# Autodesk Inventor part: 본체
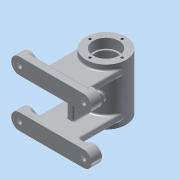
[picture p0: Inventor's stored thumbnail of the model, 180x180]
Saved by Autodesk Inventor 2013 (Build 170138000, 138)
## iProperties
Created: 2015-11
Part Number: 본체
Material: 알루미늄 6061
Document SubType Name: Modeling
Designer: user-11
Density: 2.71 g/cm^3
Mass: 359.522 g
Surface Area: 461.614 cm^2
Volume: 132.665 cm^3
Author: user-11
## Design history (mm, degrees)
sketch "스케치1"
  geometry: 1 further point
sketch "스케치2"
  geometry: 1 further point
sketch "스케치3"
  geometry: C1 r 25 at (0, 0); 1 further point
  constraints: 1 centre point, 1 coincident
  dimensions: "d0" = 50 diameter of C1
extrude "돌출1" new body sketch "스케치3" stored distance "d2" = 70; taper "d3" = 0 deg
node "작업 평면1"
sketch "스케치4"
  geometry: C1 r 21 at (0, 0); 1 further point
  constraints: 1 centre point, 1 coincident
  dimensions: "d4" = 42 diameter of C1
extrude "돌출2" cut sketch "스케치4" stored distance "d6" = 42; taper "d7" = 0 deg
sketch "스케치5"
  geometry: C1 r 25 at (0, 0) reference; C2 r 14 at (0, 0)
  constraints: 1 centre point, 1 coincident
  dimensions: "d8" = 28 diameter of C2
extrude "돌출3" cut sketch "스케치5" stored distance "d10" = 42; taper "d11" = 0 deg
sketch "스케치6"
  geometry: C1 r 14 at (0, 0) reference; C2 r 25 at (0, 0) reference; C3 r 16 at (0, 0)
  constraints: 1 centre point, 1 coincident
  dimensions: "d12" = 32 diameter of C3
extrude "돌출4" cut sketch "스케치6" distance "d14" = 12; taper "d15" = 0 deg
sketch "스케치7"
  geometry: C1 r 14 at (0, 0) reference; C2 r 25 at (0, 0) reference; C3 r 16 at (0, 0)
  constraints: 1 centre point, 1 coincident
  dimensions: "d16" = 32 diameter of C3
extrude "돌출5" cut sketch "스케치7" distance "d18" = 12; taper "d19" = 0 deg
node "작업 평면2"
node "작업 평면3"
sketch "스케치10"
  geometry: L1 (-4, 25)-(4, 25); L2 (4, 25)-(4, -25); L3 (4, -25)-(-4, -25); L4 (-4, -25)-(-4, 25); 1 further point
  constraints: 8 end point, 2 parallel, 1 horizontal, 1 perpendicular
  dimensions: "d36" = 4 distance from line of point (0, 0) L4; "d37" = 4 distance from line of point (0, 0) L2; "d38" = 50 distance of L1.end L2.end; "d39" = 25 distance from line of point (0, 0) L3
extrude "돌출8" join sketch "스케치10" stored distance "d40" = 13; taper "d41" = 0 deg
node "작업 평면4"
sketch "스케치11"
  geometry: L1 (-40, 30)-(40, 30); L2 (40, 30)-(40, -30); L3 (40, -30)-(-40, -30); L4 (-40, -30)-(-40, 30); L5 (-40, -20)-(40, -20); L6 (-40, -40)-(40, -40); L7 (40, 20)-(-40, 20); L8 (-40, 40)-(40, 40); A1 r 10 centre (-40, 30) between (-40, 40) and (-40, 20); A2 r 10 centre (40, 30) between (40, 20) and (40, 40); A3 r 10 centre (40, -30) between (40, -40) and (40, -20); A4 r 10 centre (-40, -30) between (-40, -20) and (-40, -40); 1 further point
  constraints: 16 end point, 8 point on circle, 5 point on line, 4 centre point, 4 coincident, 3 tangent, 2 parallel, 1 horizontal, 1 perpendicular
  dimensions: "d43" = 40 distance from line of point (0, 0) L4; "d44" = 80 distance of L1.start L1.end; "d45" = 30 distance from line of point (0, 0) L1; "d46" = 30 distance from line of point (0, 0) L3; "d47" = 20 diameter of A1; "d48" = 20 diameter of A2; "d49" = 20 diameter of A4; "d50" = 20 diameter of A3
extrude "돌출9" join sketch "스케치11" distance "d51" = 13; taper "d52" = 0 deg
sketch "스케치12"
  geometry: L1 (40, -20)-(-40, -20) reference; L2 (40, 20)-(-40, 20) reference; L3 (-40, 40)-(40, 40) reference; L4 (-25, 20)-(-25, 28); L5 (-25, 28)-(25, 28); L6 (25, 28)-(25, 20); L7 (-25, -20)-(-25, -28); L8 (-25, -28)-(25, -28); L9 (25, -28)-(25, -20); A1 r 10 centre (40, 30) between (40, 20) and (40, 40) reference; A2 r 10 centre (-40, 30) between (-40, 40) and (-40, 20) reference; 1 further point
  constraints: 12 end point, 5 perpendicular, 4 point on line, 1 parallel
  dimensions: "d53" = 25 distance from line of point (0, 0) L4; "d54" = 50 distance of L4.end L5.end; "d55" = 8 distance between parallel lines of L2 L5; "d56" = 25 distance from line of point (0, 0) L7; "d57" = 50 distance of L7.end L8.end; "d58" = 8 distance between parallel lines of L1 L8
extrude "돌출10" join sketch "스케치12" stored distance "d59" = 13; taper "d60" = 0 deg
sketch "스케치13"
  geometry: L1 (40, 20)-(-40, 20) reference; L2 (-40, 40)-(40, 40) reference; L3 (40, -20)-(-40, -20) reference; L4 (-40, -40)-(40, -40) reference; C1 r 10 at (40, -30); C2 r 10 at (-40, -30); C3 r 10 at (-40, 30); C4 r 10 at (40, 30); A1 r 10 centre (-40, -30) between (-40, -20) and (-40, -40) reference; A2 r 10 centre (40, -30) between (40, -40) and (40, -20) reference; A3 r 10 centre (40, 30) between (40, 20) and (40, 40) reference; A4 r 10 centre (-40, 30) between (-40, 40) and (-40, 20) reference; A5 r 10 centre (40, -30) between (40, -40) and (40, -20) reference; A6 r 10 centre (-40, -30) between (-40, -20) and (-40, -40) reference; 1 further point
  constraints: 4 centre point, 4 coincident, 4 concentric
extrude "돌출11" cut sketch "스케치13" distance "d61" = 3; taper "d62" = 0 deg
sketch "스케치14"
  geometry: L1 (40, 0)-(0, 0) reference; L2 (8.5, 10)-(31.5, 10); L3 (40, -23)-(60, -23) reference; L4 (20, 0)-(20, 10); L5 (12, 13.5)-(28, 13.5); L6 (28, 6.5)-(12, 6.5); A1 r 3.5 centre (12, 10) between (8.5, 10) and (12, 13.5); A2 r 3.5 centre (28, 10) between (31.5, 10) and (28, 13.5); 1 further point
  constraints: 8 end point, 6 point on circle, 2 centre point, 2 midpoint, 2 parallel, 2 point on line, 2 tangent, 1 perpendicular
  dimensions: "d66" = 33 distance between parallel lines of L3 L2; "d67" = 11.5 distance from line of L4 L2.start; "d68" = 11.5 distance from line of L4 L2.end; "d70" = 7 diameter of A1; "d71" = 7 diameter of A2
extrude "돌출12" cut sketch "스케치14" stored distance "d72" = 3; taper "d73" = 0 deg
sketch "스케치15"
  geometry: L1 (25, 20)-(25, 28) reference; L2 (25, 28)-(-25, 28) reference; L3 (-25, 28)-(-25, 20) reference; L4 (25, 20)-(-25, 20) reference; 1 further point
extrude "돌출13" join sketch "스케치15" distance "d74" = 3; taper "d75" = 0 deg
sketch "스케치16"
  geometry: L1 (25, -28)-(25, -20) reference; L2 (-25, -20)-(25, -20) reference; L3 (-25, -20)-(-25, -28) reference; L4 (-25, -28)-(25, -28) reference; 1 further point
extrude "돌출14" join sketch "스케치16" distance "d76" = 3; taper "d77" = 0 deg
sketch "스케치17"
  geometry: C1 r 10 at (0, 0) reference; C2 r 6 at (0, 0); C3 r 10 at (0, -60) reference; C4 r 10 at (80, -60) reference; C5 r 10 at (80, 0) reference; C6 r 6 at (80, 0); C7 r 6 at (80, -60); C8 r 6 at (0, -60); 1 further point
  constraints: 4 centre point, 4 coincident
  dimensions: "d78" = 12 diameter of C2; "d80" = 12 diameter of C6; "d81" = 12 diameter of C7; "d82" = 12 diameter of C8
extrude "돌출15" cut sketch "스케치17" distance "d83" = 4; taper "d84" = 0 deg
sketch "스케치18"
  geometry: C1 r 6 at (0, 0) reference; C2 r 6 at (-80, 0) reference; C3 r 6 at (-80, -60) reference; C4 r 6 at (0, -60) reference; C5 r 3 at (0, -60); C6 r 3 at (0, 0); C7 r 3 at (-80, 0); C8 r 3 at (-80, -60); 1 further point
  constraints: 4 centre point, 4 coincident
  dimensions: "d85" = 6 diameter of C8; "d87" = 6 diameter of C7; "d88" = 6 diameter of C6; "d89" = 6 diameter of C5
extrude "돌출16" cut sketch "스케치18" stored distance "d90" = 4; taper "d91" = 0 deg
node "작업 평면5"
sketch "스케치19"
  geometry: C1 r 5 at (0, 0); 1 further point
  constraints: 1 centre point, 1 coincident
  dimensions: "d93" = 10 diameter of C1
extrude "돌출17" join sketch "스케치19" stored distance "d95" = 4; taper "d96" = 0 deg
sketch "스케치20"
  geometry: L1 (0, 0)-(14, -24.249); L2 (0, 0)-(0, -25); L3 (14, -24.249)-(8.804, -27.249); L4 (8.804, -27.249)-(5.902, -22.222); L5 (5.902, -22.222)-(11.098, -19.222); A1 r 25 centre (0, 0) between (-25, 0) and (25, 0) reference
  constraints: 10 end point, 3 perpendicular, 1 point on circle, 1 point on line
  dimensions: "d97" = 30 deg angle of L2 L1; "d98" = 28 distance of L1.start L1.end; "d99" = 12 diameter of L4 L1
revolve "회전1" sketch "스케치20" stored, may be unused: angle "d100" = 90 deg
sketch "스케치21" dims "d101" = 40
  geometry: C1 r 25 at (0, 0) reference; C2 r 1.506 at (0, 20); 1 further point
  constraints: 1 centre point, 1 coincident, 1 vertical alignment, 2 other
hole "구멍1" sketch "스케치21" at (0, 20) diameter "d103" = 3.242; stored, may be unused: countersink angle "d107" = 90 deg, drill point angle "d109" = 118 deg; dims "d104" = 8, "d105" = 4, "d106" = 2, "d108" = 10
sketch "스케치22"
  geometry: C1 r 5 at (0, 0) reference
hole "구멍2" sketch "스케치22" at (0, 0) diameter "d113" = 5.188; stored, may be unused: countersink angle "d117" = 90 deg, drill point angle "d119" = 0 deg; dims "d114" = 10, "d115" = 4, "d116" = 2, "d118" = 10
sketch "스케치23"
  geometry: C1 r 6 at (0, 0) reference
hole "구멍3" sketch "스케치23" at (0, 0) diameter "d120" = 5.188; stored, may be unused: countersink angle "d124" = 90 deg, drill point angle "d126" = 0 deg; dims "d121" = 10, "d122" = 4, "d123" = 2, "d125" = 10
fillet "모깎기1" dims "d127" = 0.3
fillet "모깎기2" dims "d128" = 2
fillet "모깎기3" dims "d129" = 2
fillet "모깎기4" dims "d130" = 2
fillet "모깎기5" dims "d131" = 2
fillet "모깎기6" dims "d132" = 2
fillet "모깎기7" dims "d133" = 2
fillet "모깎기8" dims "d134" = 2
fillet "모깎기9" dims "d135" = 3
node "작업 평면6"
sketch "스케치24"
  geometry: L1 (-3.002, -20.739)-(-3.002, 20.739); L2 (-3.002, 20.739)-(3.002, 20.739); L3 (3.002, 20.739)-(3.002, -20.739); L4 (3.002, -20.739)-(-3.002, -20.739); L5 (0, -20.739)-(0, 20.739); L6 (-3.002, 0)-(3.002, 0); 1 further point
  constraints: 4 end point, 4 midpoint, 2 other
  dimensions: "d137" = 0 distance from line of point (0, 0) L5; "d138" = 0 distance from line of point (0, 0) L6
feature "엠보싱1" sketch "스케치24" dims "d10" = 42, "d11" = 0, "d139" = 0.5, "d140" = 0
fillet "모깎기10" dims "d141" = 2
node "솔리드1"
pattern_circular "원형 패턴1" dims angle "d111" = 360 deg
mirror "대칭1"
node "투영된 루프3"
node "투영된 루프4"
node "투영된 루프5"
node "투영된 루프6"
node "투영된 루프7"
node "투영된 루프8"
node "투영된 루프9"
node "투영된 루프10"
other parameters: "d20" = -68, "d31" = -45, "d42" = -68, "d92" = 96, "d136" = -134.5
